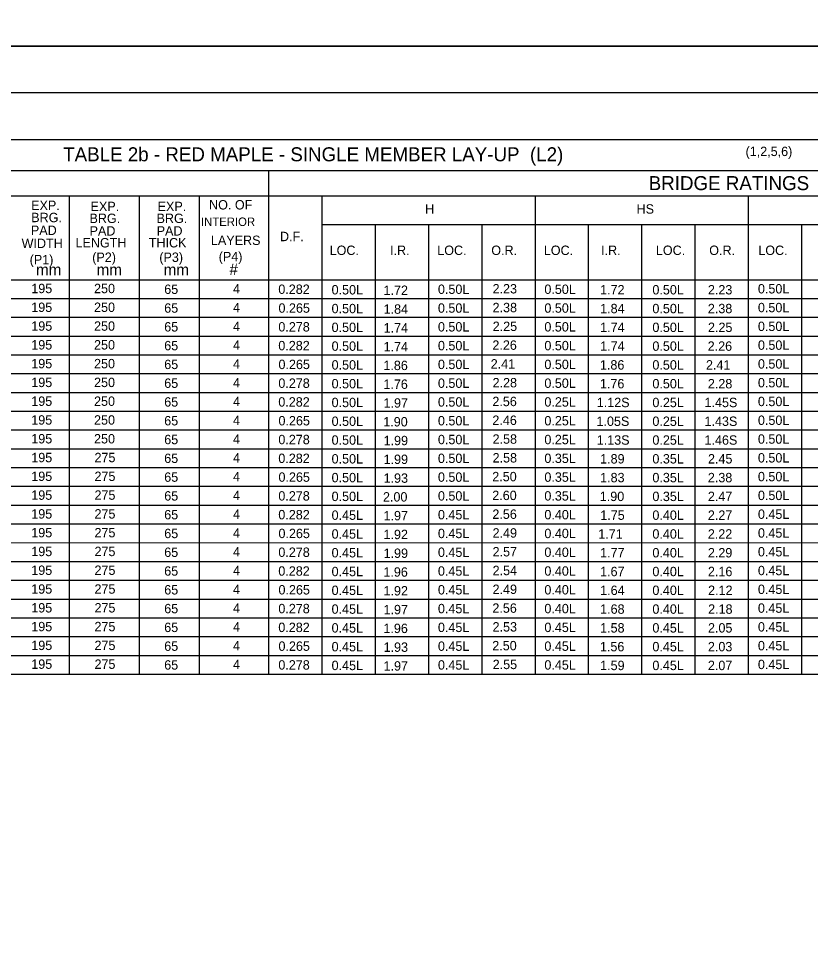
# Model space of a CAD drawing. Extents: x -5022 to -159, y 1126 to 7226.
# Drawn here: x -4365.7 to -4112.8, y 4400.9 to 4698.6 of the extents above; entities that cross this region are included whole.
import ezdxf

# ---------------------------------------------------------------- set-up
doc = ezdxf.new("R2010")
doc.units = 0
for name, color, linetype in [('2', 7, 'Continuous'), ('3', 7, 'Continuous'), ('PLT-BNDY', 7, 'Continuous')]:
    doc.layers.add(name, color=color, linetype=linetype)

msp = doc.modelspace()

# ---------------------------------------------------------------- linework, layer by layer
at = {"layer": '2'}
msp.add_line((-3855.13, 4674.81), (-4641.13, 4674.81), dxfattribs=at)
at = {"layer": '3'}
for p, q in [((-4608.08, 4659.97), (-3894.35, 4659.97)), ((-4608.08, 4650.05), (-3894.35, 4650.05)), ((-4285.83, 4650.05), (-4285.83, 4489.16)), ((-4608.08, 4641.98), (-3894.35, 4641.98)), ((-4349.52, 4641.98), (-4349.52, 4489.16)), ((-4327.21, 4641.98), (-4327.21, 4489.16)), ((-4308.07, 4641.98), (-4308.07, 4489.16)), ((-4268.81, 4641.98), (-4268.81, 4489.16)), ((-4200.72, 4641.98), (-4200.72, 4489.16)), ((-4132.64, 4641.98), (-4132.64, 4489.17)), ((-4268.81, 4632.77), (-3894.35, 4632.77)), ((-4251.78, 4632.77), (-4251.78, 4489.16)), ((-4234.76, 4632.77), (-4234.76, 4489.16)), ((-4234.76, 4632.77), (-4234.76, 4489.16)), ((-4217.74, 4632.77), (-4217.74, 4489.16)), ((-4200.72, 4632.77), (-4200.72, 4489.16)), ((-4183.7, 4632.77), (-4183.7, 4489.16)), ((-4166.68, 4632.77), (-4166.68, 4489.17)), ((-4166.68, 4632.77), (-4166.68, 4489.17)), ((-4149.66, 4632.77), (-4149.66, 4489.17)), ((-4132.64, 4632.77), (-4132.64, 4489.17)), ((-4115.62, 4632.77), (-4115.62, 4489.17)), ((-4608.08, 4615.17), (-3894.35, 4615.17)), ((-4590.61, 4609.17), (-3894.35, 4609.17)), ((-4590.61, 4603.17), (-3894.35, 4603.17)), ((-4608.08, 4597.17), (-3894.35, 4597.17)), ((-4590.61, 4591.17), (-3894.35, 4591.17)), ((-4590.61, 4585.17), (-3894.35, 4585.17)), ((-4608.08, 4579.16), (-3894.35, 4579.17)), ((-4590.61, 4573.16), (-3894.35, 4573.17)), ((-4590.61, 4567.17), (-3894.35, 4567.17)), ((-4608.08, 4561.17), (-3894.35, 4561.17)), ((-4590.61, 4555.17), (-3894.35, 4555.17)), ((-4590.61, 4549.17), (-3894.35, 4549.17)), ((-4608.08, 4543.17), (-3894.35, 4543.17)), ((-4590.61, 4537.17), (-3894.35, 4537.17)), ((-4590.61, 4531.16), (-3894.35, 4531.17)), ((-4608.08, 4525.16), (-3894.35, 4525.16)), ((-4590.61, 4519.16), (-3894.35, 4519.17)), ((-4590.61, 4513.16), (-3894.35, 4513.17)), ((-4608.08, 4507.17), (-3894.35, 4507.17)), ((-4590.61, 4501.16), (-3894.35, 4501.17)), ((-4590.61, 4495.16), (-3894.35, 4495.17)), ((-4608.08, 4489.16), (-3894.35, 4489.17))]:
    msp.add_line(p, q, dxfattribs=at)
at = {"layer": 'PLT-BNDY'}
for points in [[(-4681.13, 5283.81), (-3840.13, 5283.81), (-3840.13, 4689.81), (-4681.13, 4689.81)], [(-4681.13, 4689.81), (-3840.13, 4689.81), (-3840.13, 4095.81), (-4681.13, 4095.81)]]:
    msp.add_lwpolyline(points, close=True, dxfattribs=at)

# ---------------------------------------------------------------- texts
at = {"layer": '2'}
for s, height, p in [('TABLE 2b - RED MAPLE - SINGLE MEMBER LAY-UP  (L2)', 4.4793, (-4351.46, 4652.98)), ('(1,2,5,6)', 3, (-4133.46, 4654.66)), ('BRIDGE RATINGS', 4.4793, (-4164.4, 4643.77)), ('EXP.', 3, (-4361.69, 4637.42)), ('EXP.', 3, (-4342.71, 4637.06)), ('EXP.', 3, (-4321.29, 4637.06)), ('NO. OF', 3, (-4304.85, 4637.59)), ('H', 3, (-4235.83, 4636.26)), ('HS', 3, (-4168.28, 4636.26)), ('BRG.', 3, (-4361.67, 4633.54)), ('BRG.', 3, (-4343.06, 4633.27)), ('BRG.', 3, (-4321.63, 4633.27)), ('INTERIOR', 2.708, (-4307.45, 4632.32)), ('PAD', 3, (-4361.78, 4629.45)), ('PAD', 3, (-4343.02, 4629.26)), ('PAD', 3, (-4321.59, 4629.26)), ('WIDTH', 3, (-4364.74, 4625.28)), ('LENGTH', 3, (-4347.51, 4625.47)), ('THICK', 3, (-4324.11, 4625.47)), ('LAYERS', 3, (-4304.26, 4626.25)), ('D.F.', 3, (-4282.2, 4627.47)), ('LOC.', 3, (-4266.33, 4623.06)), ('I.R.', 3, (-4247.03, 4623.06)), ('LOC.', 3, (-4231.95, 4623.06)), ('O.R.', 3, (-4214.69, 4623.06)), ('LOC.', 3, (-4197.91, 4623.06)), ('I.R.', 3, (-4179.61, 4623.06)), ('LOC.', 3, (-4162.11, 4623.06)), ('O.R.', 3, (-4145.06, 4623.06)), ('LOC.', 3, (-4129.38, 4623.06)), ('(P1)', 3, (-4362.17, 4620.09)), ('(P2)', 3, (-4342.18, 4620.84)), ('(P3)', 3, (-4320.75, 4620.84)), ('(P4)', 3, (-4301.78, 4621.06)), ('mm', 3.629, (-4360.13, 4616.55)), ('mm', 3.629, (-4340.78, 4616.55)), ('mm', 3.629, (-4319.35, 4616.55)), ('#', 3.63, (-4298.34, 4616.68)), ('195', 3, (-4361.66, 4610.86)), ('250', 3, (-4341.6, 4610.86)), ('65', 3, (-4319.18, 4610.62)), ('4', 3, (-4297.19, 4610.77)), ('0.282', 3, (-4282.73, 4610.62)), ('0.50L', 3, (-4265.71, 4610.45)), ('1.72', 3, (-4249.12, 4610.29)), ('0.50L', 3, (-4231.74, 4610.62)), ('2.23', 3, (-4214.28, 4610.77)), ('0.50L', 3, (-4197.73, 4610.62)), ('1.72', 3, (-4179.94, 4610.45)), ('0.50L', 3, (-4163.22, 4610.45)), ('2.23', 3, (-4145.49, 4610.45)), ('0.50L', 3, (-4129.51, 4610.77)), ('195', 3, (-4361.66, 4604.86)), ('250', 3, (-4341.6, 4604.86)), ('65', 3, (-4319.18, 4604.61)), ('4', 3, (-4297.19, 4604.77)), ('0.265', 3, (-4282.68, 4604.61)), ('0.50L', 3, (-4265.71, 4604.45)), ('1.84', 3, (-4249.09, 4604.29)), ('0.50L', 3, (-4231.74, 4604.61)), ('2.38', 3, (-4214.28, 4604.77)), ('0.50L', 3, (-4197.73, 4604.61)), ('1.84', 3, (-4179.91, 4604.45)), ('0.50L', 3, (-4163.22, 4604.45)), ('2.38', 3, (-4145.5, 4604.45)), ('0.50L', 3, (-4129.51, 4604.77)), ('195', 3, (-4361.66, 4598.86)), ('250', 3, (-4341.6, 4598.86)), ('65', 3, (-4319.18, 4598.61)), ('4', 3, (-4297.19, 4598.77)), ('0.278', 3, (-4282.72, 4598.61)), ('0.50L', 3, (-4265.71, 4598.45)), ('1.74', 3, (-4249.09, 4598.29)), ('0.50L', 3, (-4231.74, 4598.61)), ('2.25', 3, (-4214.24, 4598.77)), ('0.50L', 3, (-4197.73, 4598.61)), ('1.74', 3, (-4179.91, 4598.45)), ('0.50L', 3, (-4163.22, 4598.45)), ('2.25', 3, (-4145.46, 4598.45)), ('0.50L', 3, (-4129.51, 4598.77)), ('195', 3, (-4361.66, 4592.86)), ('250', 3, (-4341.6, 4592.86)), ('65', 3, (-4319.18, 4592.61)), ('4', 3, (-4297.19, 4592.77)), ('0.282', 3, (-4282.73, 4592.61)), ('0.50L', 3, (-4265.71, 4592.45)), ('0.50L', 3, (-4231.74, 4592.61)), ('2.26', 3, (-4214.34, 4592.77)), ('0.50L', 3, (-4197.73, 4592.61)), ('1.74', 3, (-4179.91, 4592.45)), ('0.50L', 3, (-4163.22, 4592.45)), ('2.26', 3, (-4145.56, 4592.45)), ('0.50L', 3, (-4129.51, 4592.77)), ('1.74', 3, (-4249.09, 4592.29)), ('195', 3, (-4361.66, 4586.86)), ('250', 3, (-4341.6, 4586.86)), ('65', 3, (-4319.18, 4586.61)), ('4', 3, (-4297.19, 4586.77)), ('0.265', 3, (-4282.68, 4586.61)), ('0.50L', 3, (-4265.71, 4586.45)), ('0.50L', 3, (-4231.74, 4586.61)), ('2.41', 3, (-4214.88, 4586.77)), ('0.50L', 3, (-4197.73, 4586.61)), ('1.86', 3, (-4179.98, 4586.45)), ('0.50L', 3, (-4163.22, 4586.45)), ('2.41', 3, (-4146.1, 4586.45)), ('0.50L', 3, (-4129.51, 4586.77)), ('1.86', 3, (-4249.16, 4586.29)), ('195', 3, (-4361.66, 4580.86)), ('250', 3, (-4341.6, 4580.86)), ('65', 3, (-4319.18, 4580.61)), ('4', 3, (-4297.19, 4580.77)), ('0.278', 3, (-4282.72, 4580.61)), ('0.50L', 3, (-4265.71, 4580.45)), ('0.50L', 3, (-4231.74, 4580.61)), ('2.28', 3, (-4214.28, 4580.77)), ('0.50L', 3, (-4197.73, 4580.61)), ('1.76', 3, (-4179.98, 4580.45)), ('0.50L', 3, (-4163.22, 4580.45)), ('2.28', 3, (-4145.5, 4580.45)), ('0.50L', 3, (-4129.51, 4580.77)), ('1.76', 3, (-4249.16, 4580.29)), ('195', 3, (-4361.66, 4574.86)), ('250', 3, (-4341.6, 4574.86)), ('65', 3, (-4319.18, 4574.62)), ('4', 3, (-4297.19, 4574.77)), ('0.282', 3, (-4282.73, 4574.62)), ('0.50L', 3, (-4265.71, 4574.45)), ('0.50L', 3, (-4231.74, 4574.62)), ('2.56', 3, (-4214.34, 4574.77)), ('0.25L', 3, (-4197.73, 4574.62)), ('1.12S', 3, (-4181, 4574.45)), ('0.25L', 3, (-4163.22, 4574.45)), ('1.45S', 3, (-4146.57, 4574.45)), ('0.50L', 3, (-4129.51, 4574.77)), ('1.97', 3, (-4249.11, 4574.29)), ('195', 3, (-4361.66, 4568.86)), ('250', 3, (-4341.6, 4568.86)), ('65', 3, (-4319.18, 4568.62)), ('4', 3, (-4297.19, 4568.77)), ('0.265', 3, (-4282.68, 4568.62)), ('0.50L', 3, (-4231.74, 4568.62)), ('2.46', 3, (-4214.34, 4568.77)), ('0.25L', 3, (-4197.73, 4568.62)), ('0.50L', 3, (-4129.51, 4568.77)), ('0.50L', 3, (-4265.71, 4568.45)), ('1.90', 3, (-4249.2, 4568.29)), ('1.05S', 3, (-4181.08, 4568.45)), ('0.25L', 3, (-4163.22, 4568.45)), ('1.43S', 3, (-4146.57, 4568.45)), ('195', 3, (-4361.66, 4562.86)), ('250', 3, (-4341.6, 4562.86)), ('65', 3, (-4319.18, 4562.62)), ('4', 3, (-4297.19, 4562.77)), ('0.278', 3, (-4282.72, 4562.61)), ('0.50L', 3, (-4231.74, 4562.61)), ('2.58', 3, (-4214.28, 4562.77)), ('0.25L', 3, (-4197.73, 4562.61)), ('0.50L', 3, (-4129.51, 4562.77)), ('0.50L', 3, (-4265.71, 4562.45)), ('1.99', 3, (-4249.1, 4562.29)), ('1.13S', 3, (-4181, 4562.45)), ('0.25L', 3, (-4163.22, 4562.45)), ('1.46S', 3, (-4146.57, 4562.45)), ('195', 3, (-4361.66, 4556.86)), ('275', 3, (-4341.46, 4556.86)), ('65', 3, (-4319.18, 4556.61)), ('4', 3, (-4297.19, 4556.77)), ('0.282', 3, (-4282.73, 4556.61)), ('0.50L', 3, (-4231.74, 4556.61)), ('2.58', 3, (-4214.28, 4556.77)), ('0.35L', 3, (-4197.73, 4556.61)), ('0.50L', 3, (-4129.51, 4556.77)), ('0.50L', 3, (-4265.71, 4556.45)), ('1.99', 3, (-4249.1, 4556.29)), ('1.89', 3, (-4179.92, 4556.45)), ('0.35L', 3, (-4163.22, 4556.45)), ('2.45', 3, (-4145.46, 4556.45)), ('195', 3, (-4361.66, 4550.86)), ('275', 3, (-4341.46, 4550.86)), ('4', 3, (-4297.19, 4550.77)), ('2.50', 3, (-4214.38, 4550.77)), ('0.50L', 3, (-4129.51, 4550.77)), ('65', 3, (-4319.18, 4550.61)), ('0.265', 3, (-4282.68, 4550.61)), ('0.50L', 3, (-4265.71, 4550.45)), ('1.93', 3, (-4249.1, 4550.29)), ('0.50L', 3, (-4231.74, 4550.61)), ('0.35L', 3, (-4197.73, 4550.61)), ('1.83', 3, (-4179.92, 4550.45)), ('0.35L', 3, (-4163.22, 4550.45)), ('2.38', 3, (-4145.5, 4550.45)), ('195', 3, (-4361.66, 4544.86)), ('275', 3, (-4341.46, 4544.86)), ('4', 3, (-4297.19, 4544.77)), ('2.60', 3, (-4214.38, 4544.77)), ('0.50L', 3, (-4129.51, 4544.77)), ('65', 3, (-4319.18, 4544.61)), ('0.278', 3, (-4282.72, 4544.61)), ('0.50L', 3, (-4265.71, 4544.45)), ('2.00', 3, (-4249.29, 4544.29)), ('0.50L', 3, (-4231.74, 4544.61)), ('0.35L', 3, (-4197.73, 4544.61)), ('1.90', 3, (-4180.03, 4544.45)), ('0.35L', 3, (-4163.22, 4544.45)), ('2.47', 3, (-4145.5, 4544.45)), ('195', 3, (-4361.66, 4538.86)), ('275', 3, (-4341.46, 4538.86)), ('4', 3, (-4297.19, 4538.77)), ('2.56', 3, (-4214.34, 4538.77)), ('0.45L', 3, (-4129.51, 4538.77)), ('65', 3, (-4319.18, 4538.61)), ('0.282', 3, (-4282.73, 4538.61)), ('0.45L', 3, (-4265.71, 4538.45)), ('1.97', 3, (-4249.11, 4538.29)), ('0.45L', 3, (-4231.74, 4538.61)), ('0.40L', 3, (-4197.73, 4538.61)), ('1.75', 3, (-4179.88, 4538.45)), ('0.40L', 3, (-4163.22, 4538.45)), ('2.27', 3, (-4145.5, 4538.45)), ('195', 3, (-4361.66, 4532.86)), ('275', 3, (-4341.46, 4532.86)), ('2.49', 3, (-4214.28, 4532.77)), ('0.45L', 3, (-4129.51, 4532.77)), ('65', 3, (-4319.18, 4532.61)), ('4', 3, (-4297.19, 4532.77)), ('0.265', 3, (-4282.68, 4532.61)), ('0.45L', 3, (-4265.71, 4532.45)), ('1.92', 3, (-4249.12, 4532.29)), ('0.45L', 3, (-4231.74, 4532.61)), ('0.40L', 3, (-4197.73, 4532.61)), ('1.71', 3, (-4180.52, 4532.45)), ('0.40L', 3, (-4163.22, 4532.45)), ('2.22', 3, (-4145.51, 4532.45)), ('195', 3, (-4361.66, 4526.86)), ('275', 3, (-4341.46, 4526.86)), ('65', 3, (-4319.18, 4526.61)), ('4', 3, (-4297.19, 4526.77)), ('0.278', 3, (-4282.72, 4526.61)), ('0.45L', 3, (-4265.71, 4526.45)), ('1.99', 3, (-4249.1, 4526.29)), ('0.45L', 3, (-4231.74, 4526.61)), ('2.57', 3, (-4214.28, 4526.77)), ('0.40L', 3, (-4197.73, 4526.61)), ('1.77', 3, (-4179.93, 4526.45)), ('0.40L', 3, (-4163.22, 4526.45)), ('2.29', 3, (-4145.5, 4526.45)), ('0.45L', 3, (-4129.51, 4526.77)), ('195', 3, (-4361.66, 4520.86)), ('275', 3, (-4341.46, 4520.86)), ('65', 3, (-4319.18, 4520.61)), ('4', 3, (-4297.19, 4520.77)), ('0.282', 3, (-4282.73, 4520.61)), ('0.45L', 3, (-4265.71, 4520.45)), ('1.96', 3, (-4249.16, 4520.29)), ('0.45L', 3, (-4231.74, 4520.61)), ('2.54', 3, (-4214.27, 4520.77)), ('0.40L', 3, (-4197.73, 4520.61)), ('1.67', 3, (-4179.93, 4520.45)), ('0.40L', 3, (-4163.22, 4520.45)), ('2.16', 3, (-4145.48, 4520.45)), ('0.45L', 3, (-4129.51, 4520.77)), ('195', 3, (-4361.66, 4514.86)), ('275', 3, (-4341.46, 4514.86)), ('65', 3, (-4319.18, 4514.61)), ('4', 3, (-4297.19, 4514.77)), ('0.265', 3, (-4282.68, 4514.61)), ('0.45L', 3, (-4265.71, 4514.45)), ('1.92', 3, (-4249.12, 4514.29)), ('0.45L', 3, (-4231.74, 4514.61)), ('2.49', 3, (-4214.28, 4514.77)), ('0.40L', 3, (-4197.73, 4514.61)), ('1.64', 3, (-4179.91, 4514.45)), ('0.40L', 3, (-4163.22, 4514.45)), ('2.12', 3, (-4145.43, 4514.45)), ('0.45L', 3, (-4129.51, 4514.77)), ('195', 3, (-4361.66, 4508.86)), ('275', 3, (-4341.46, 4508.86)), ('65', 3, (-4319.18, 4508.61)), ('4', 3, (-4297.19, 4508.77)), ('0.278', 3, (-4282.72, 4508.61)), ('0.45L', 3, (-4265.71, 4508.45)), ('1.97', 3, (-4249.11, 4508.29)), ('0.45L', 3, (-4231.74, 4508.61)), ('2.56', 3, (-4214.34, 4508.77)), ('0.40L', 3, (-4197.73, 4508.61)), ('1.68', 3, (-4179.92, 4508.45)), ('0.40L', 3, (-4163.22, 4508.45)), ('2.18', 3, (-4145.42, 4508.45)), ('0.45L', 3, (-4129.51, 4508.77)), ('195', 3, (-4361.66, 4502.86)), ('275', 3, (-4341.46, 4502.86)), ('65', 3, (-4319.18, 4502.61)), ('4', 3, (-4297.19, 4502.77)), ('0.282', 3, (-4282.73, 4502.61)), ('0.45L', 3, (-4265.71, 4502.45)), ('1.96', 3, (-4249.16, 4502.29)), ('0.45L', 3, (-4231.74, 4502.61)), ('2.53', 3, (-4214.28, 4502.77)), ('0.45L', 3, (-4197.73, 4502.61)), ('1.58', 3, (-4179.92, 4502.45)), ('0.45L', 3, (-4163.22, 4502.45)), ('2.05', 3, (-4145.46, 4502.45)), ('0.45L', 3, (-4129.51, 4502.77)), ('195', 3, (-4361.66, 4496.86)), ('275', 3, (-4341.46, 4496.86)), ('65', 3, (-4319.18, 4496.61)), ('4', 3, (-4297.19, 4496.77)), ('0.265', 3, (-4282.68, 4496.61)), ('0.45L', 3, (-4265.71, 4496.45)), ('1.93', 3, (-4249.1, 4496.29)), ('0.45L', 3, (-4231.74, 4496.61)), ('2.50', 3, (-4214.38, 4496.77)), ('0.45L', 3, (-4197.73, 4496.61)), ('1.56', 3, (-4179.98, 4496.45)), ('0.45L', 3, (-4163.22, 4496.45)), ('2.03', 3, (-4145.49, 4496.45)), ('0.45L', 3, (-4129.51, 4496.77)), ('195', 3, (-4361.66, 4490.86)), ('275', 3, (-4341.46, 4490.86)), ('65', 3, (-4319.18, 4490.61)), ('4', 3, (-4297.19, 4490.77)), ('0.278', 3, (-4282.72, 4490.61)), ('0.45L', 3, (-4265.71, 4490.45)), ('1.97', 3, (-4249.11, 4490.29)), ('0.45L', 3, (-4231.74, 4490.61)), ('2.55', 3, (-4214.24, 4490.77)), ('0.45L', 3, (-4197.73, 4490.61)), ('1.59', 3, (-4179.92, 4490.45)), ('0.45L', 3, (-4163.22, 4490.45)), ('2.07', 3, (-4145.5, 4490.45)), ('0.45L', 3, (-4129.51, 4490.77))]:
    msp.add_text(s, height=height, dxfattribs=at).set_placement(p)

doc.saveas('drawing.dxf')
